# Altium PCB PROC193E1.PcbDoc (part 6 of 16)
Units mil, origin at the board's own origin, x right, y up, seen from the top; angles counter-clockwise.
Board outline 7700 x 2300 mil, 6 copper layers (Top Layer, GND 1, SIG 1, PWR, GND 2, Bottom Layer), stack 60.98 mil thick; 946 components, 667 nets, 9401 pads, 1730 vias.
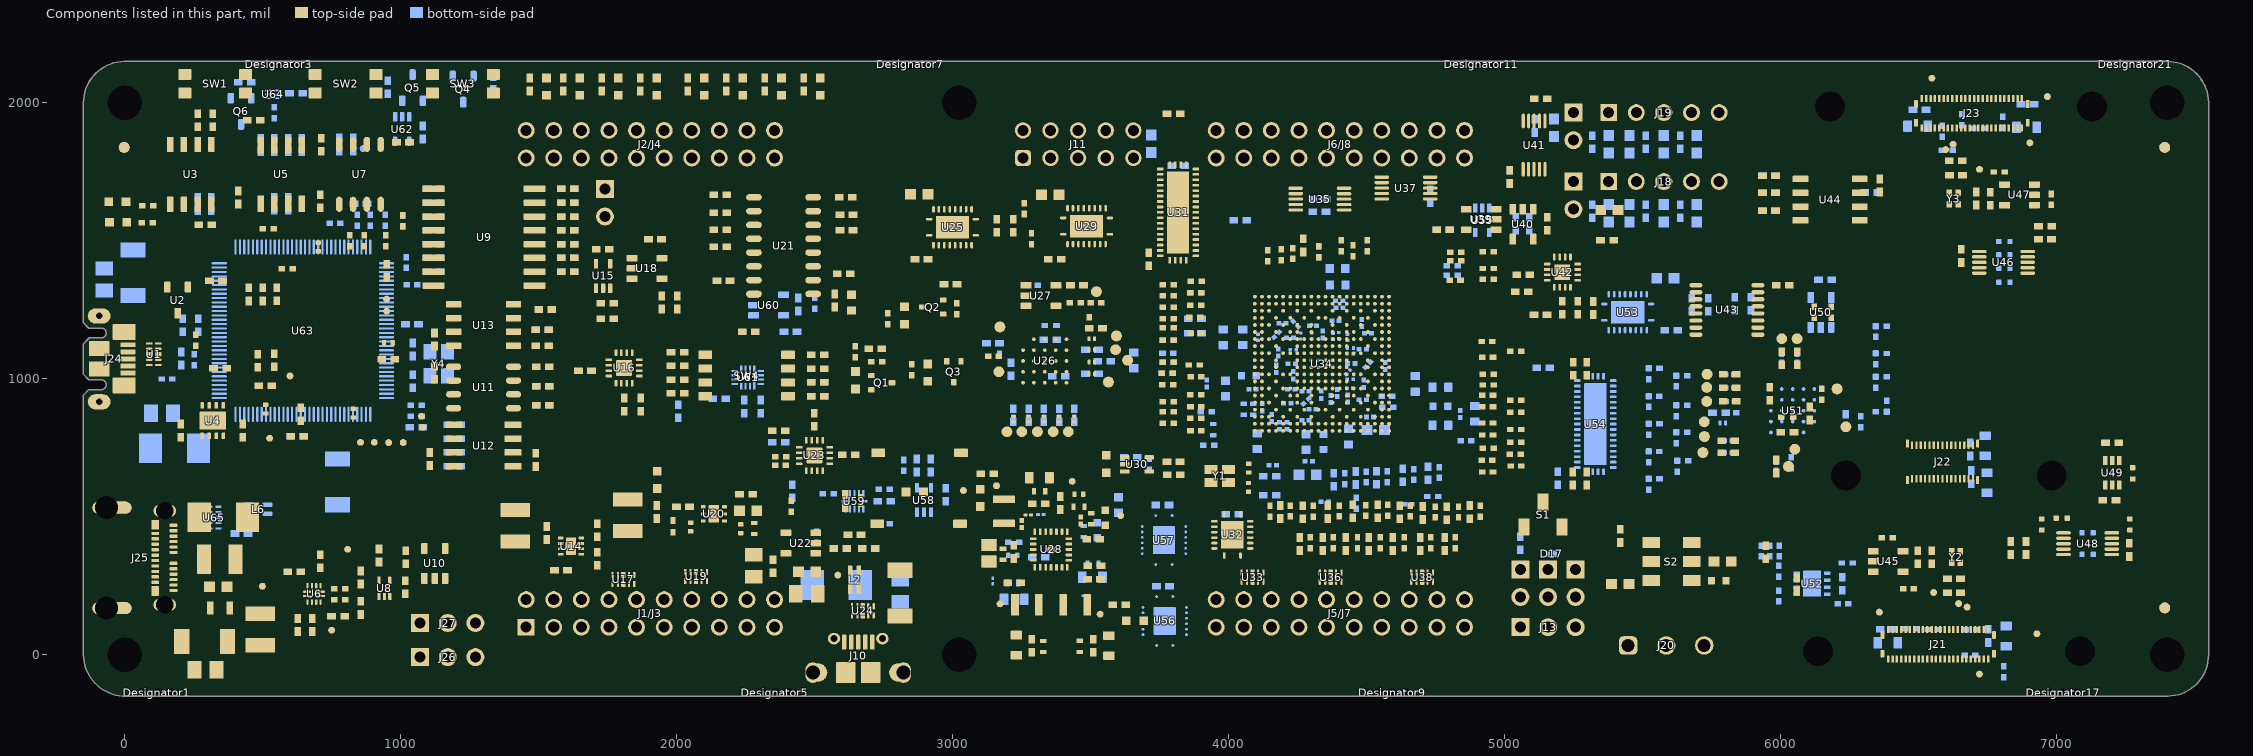
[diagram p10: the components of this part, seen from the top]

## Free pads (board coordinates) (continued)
  round 4 on Mech16: 1(-109,1797) 1(-109,1797) 1(-107,1890) 1(-107,1890) 1(-100.21,1451.4) 1(-100.21,1451.4) 1(-100.21,1501.4) 1(-100.21,1501.4) 1(-96.98,1641.17) 1(-96.98,1641.17) 1(-94.03,1567.07) 1(-94.03,1567.07) 1(-92.91,1280.67) 1(-92.91,1280.67) 1(-51.58,1279.52) 1(-51.58,1279.52) 1(-50.21,1451.4) 1(-50.21,1451.4) 1(-50.21,1501.4) 1(-50.21,1501.4) 1(10.71,1255.26) 1(10.71,1255.26) 1(55.5,1255.13) 1(55.5,1255.13) 1(57.05,333.66) 1(57.05,333.66) 1(57.05,369.66) 1(57.05,369.66) 1(58.94,1123.11) 1(58.94,1123.11) 1(69.85,292.13) 1(69.85,292.13) 1(76.14,1007.82) 1(76.14,1007.82) 1(80.09,231.18) 1(80.09,231.18) 1(80.09,471.33) 1(80.09,471.33) 1(95.75,923.11) 1(95.75,923.11) 1(104.21,999.27) 1(104.21,999.27) 1(130.97,1565.68) 1(130.97,1565.68) 1(133.02,1626.75) 1(133.02,1626.75) 1(140.74,333.26) 1(140.74,333.26) 1(140.74,369.26) 1(140.74,369.26) 1(142.29,400.06) 1(142.29,400.06) 1(143.88,424.98) 1(143.88,424.98) 1(144,473) 1(144,473) 1(144,282.09) 1(144,282.09) 1(145,2110) 1(145,2110) 1(155,1370.91) 1(155,1370.91) 1(160,1041.39) 1(160,1041.39) 1(160,1077.39) 1(160,1077.39) 1(163.9,1892.59) 1(163.9,1892.59) 1(164,1678) 1(164,1678) 1(165,1203.44) 1(165,1203.44) 1(174.9,1129.75) 1(174.9,1129.75) 1(175.1,-66.69) 1(175.1,-66.69) 1(175.1,-38.02) 1(175.1,-38.02) 1(183.7,107.99) 1(183.7,107.99) 1(198.93,220.48) 1(198.93,220.48) 1(202.72,681.67) 1(202.72,681.67) 1(203.76,-66.69) 1(203.76,-66.69) 1(203.76,-38.02) 1(203.76,-38.02) 1(212.36,107.99) 1(212.36,107.99) 1(212.56,390.13) 1(212.56,390.13) 1(213.57,1689.72) 1(213.57,1689.72) 1(218.04,259.4) 1(218.04,259.4) 1(223.39,199.95) 1(223.39,199.95) 1(231.43,1558.65) 1(231.43,1558.65) 1(240.71,229.19) 1(240.71,229.19) 1(240.71,292.2) 1(240.71,292.2) 1(240.71,325.66) 1(240.71,325.66) 1(241.5,360.53) 1(241.5,360.53) 1(243.58,167.7) 1(243.58,167.7) 1(243.98,959.49) 1(243.98,959.49) 1(245,993.11) 1(245,993.11) 1(261.88,2035.35) 1(261.88,2035.35) 1(263.8,258.72) 1(263.8,258.72) 1(264.06,1690.56) 1(264.06,1690.56) 1(264.16,200.22) 1(264.16,200.22) 1(265.82,1248.11) 1(265.82,1248.11) 1(274.55,1355.66) 1(274.55,1355.66) 1(280.11,952.74) 1(280.11,952.74) 1(291.26,1020) 1(291.26,1020) 1(294.7,1182.06) 1(294.7,1182.06) 1(296.51,1127.49) 1(296.51,1127.49) 1(296.51,1323.98) 1(296.51,1323.98) 1(315,1524) 1(315,1524) 1(318.73,1989.01) 1(318.73,1989.01) 1(319,-115) 1(319,-115) 1(350.09,1913.44) 1(350.09,1913.44) 1(353.19,2035.93) 1(353.19,2035.93) 1(377.93,2074.5) 1(377.93,2074.5) 1(382.15,1633.29) 1(382.15,1633.29) 1(386.18,977.52) 1(386.18,977.52) 1(390,1166.68) 1(390,1166.68) 1(390,1355.66) 1(390,1355.66) 1(395,826.17) 1(395,826.17) 1(395,1078.07) 1(395,1078.07) 1(400,1038.47) 1(400,1038.47) 1(408.56,246.92) 1(408.56,246.92) 1(408.56,275.59) 1(408.56,275.59) 1(419,-115) 1(419,-115) 1(421.14,1884.01) 1(421.14,1884.01) 1(423.01,-47.42) 1(423.01,-47.42) 1(423.01,-18.76) 1(423.01,-18.76) 1(434.84,276.57) 1(434.84,276.57) 1(436.18,977.52) 1(436.18,977.52) 1(444.71,1680.54) 1(444.71,1680.54) 1(448.04,304.9) 1(448.04,304.9) 1(448.04,333.56) 1(448.04,333.56) 1(448.04,362.23) 1(448.04,362.23) 1(448.04,390.89) 1(448.04,390.89) 1(450.31,190.05) 1(450.31,190.05) 1(450.31,218.71) 1(450.31,218.71) 1(451.67,-47.42) 1(451.67,-47.42) 1(451.67,-18.76) 1(451.67,-18.76) 1(453.93,1387.9) 1(453.93,1387.9) 1(457.27,797.27) 1(457.27,797.27) 1(457.48,764.8) 1(457.48,764.8) 1(461.61,1870.74) 1(461.61,1870.74) 1(476.71,304.9) 1(476.71,304.9) 1(476.71,333.56) 1(476.71,333.56) 1(476.71,362.23) 1(476.71,362.23) 1(476.71,390.89) 1(476.71,390.89) 1(478.98,190.05) 1(478.98,190.05) 1(478.98,218.71) 1(478.98,218.71) 1(480.33,-47.42) 1(480.33,-47.42) 1(480.33,-18.76) 1(480.33,-18.76) 1(480.59,1413.28) 1(480.59,1413.28) 1(480.73,784.53) 1(480.73,784.53) 1(481.97,1122.33) 1(481.97,1122.33) 1(485.53,2102.28) 1(485.53,2102.28) 1(488.92,2041.18) 1(488.92,2041.18) 1(489.98,1959.79) 1(489.98,1959.79) 1(496.08,823.57) 1(496.08,823.57) 1(499.83,1519.85) 1(499.83,1519.85) 1(500.77,1367.28) 1(500.77,1367.28) 1(504.73,481.52) 1(504.73,481.52) 1(507.64,190.05) 1(507.64,190.05) 1(507.64,218.71) 1(507.64,218.71) 1(509,-47.42) 1(509,-47.42) 1(509,-18.76) 1(509,-18.76) 1(510.2,934.01) 1(510.2,934.01) 1(513.14,2068) 1(513.14,2068) 1(519,-115) 1(519,-115) 1(530.73,1008.1) 1(530.73,1008.1) 1(536.3,190.05) 1(536.3,190.05) 1(536.3,218.71) 1(536.3,218.71) 1(536.3,247.37) 1(536.3,247.37) 1(537.66,-47.42) 1(537.66,-47.42) 1(537.66,-18.76) 1(537.66,-18.76) 1(537.79,1365.91) 1(537.79,1365.91) 1(539.2,416.22) 1(539.2,416.22) 1(539.2,1519.68) 1(539.2,1519.68) 1(541.82,1907.98) 1(541.82,1907.98) 1(541.97,1124.26) 1(541.97,1124.26) 1(541.97,1572.04) 1(541.97,1572.04) 1(563.03,1429.89) 1(563.03,1429.89) 1(564.96,190.05) 1(564.96,190.05) 1(564.96,218.71) 1(564.96,218.71) 1(573.46,1983.42) 1(573.46,1983.42) 1(590.41,340.66) 1(590.41,340.66) 1(591.69,1689.01) 1(591.69,1689.01) 1(591.82,1570.46) 1(591.82,1570.46) 1(591.82,1907.98) 1(591.82,1907.98) 1(597.02,2064.5) 1(597.02,2064.5) 1(598.48,823) 1(598.48,823) 1(598.48,1043.83) 1(598.48,1043.83) 1(608.14,1979.7) 1(608.14,1979.7) 1(608.19,1427.13) 1(608.19,1427.13) 1(619,-115) 1(619,-115) 1(622.03,205.39) 1(622.03,205.39) 1(622.36,237.37) 1(622.36,237.37) 1(627.14,50.91) 1(627.14,50.91) 1(636.73,333.56) 1(636.73,333.56) 1(637.63,927.56) 1(637.63,927.56) 1(641.56,1907.98) 1(641.56,1907.98) 1(641.82,1573.46) 1(641.82,1573.46) 1(650.96,1410.49) 1(650.96,1410.49) 1(654.75,1363.22) 1(654.75,1363.22) 1(663.07,822.16) 1(663.07,822.16) 1(668,-60) 1(668,-60) 1(673.06,1870.74) 1(673.06,1870.74) 1(679.97,48.23) 1(679.97,48.23) 1(680.93,1825.27) 1(680.93,1825.27) 1(689.76,1992.44) 1(689.76,1992.44) 1(690.5,798) 1(690.5,798) 1(693.44,275.6) 1(693.44,275.6) 1(700.81,1429.87) 1(700.81,1429.87) 1(700.81,1526.55) 1(700.81,1526.55) 1(708.51,543.88) 1(708.51,543.88) 1(708.51,709.23) 1(708.51,709.23) 1(708.51,1582.82) 1(708.51,1582.82) 1(711.42,1905.81) 1(711.42,1905.81) 1(719,-115) 1(719,-115) 1(740,951.65) 1(740,951.65) 1(740,987.65) 1(740,987.65) 1(740.37,1667.24) 1(740.37,1667.24) 1(741.85,363.15) 1(741.85,363.15) 1(742.1,1536.63) 1(742.1,1536.63) 1(748.05,1429.87) 1(748.05,1429.87) 1(768,-60) 1(768,-60) 1(776.99,1908.23) 1(776.99,1908.23) 1(779,2072) 1(779,2072) 1(798.91,167.7) 1(798.91,167.7) 1(804.99,1587.77) 1(804.99,1587.77) 1(815,1415.6) 1(815,1415.6) 1(815.77,1545.65) 1(815.77,1545.65) 1(819,-115) 1(819,-115) 1(826.42,918.87) 1(826.42,918.87) 1(827.25,1907.72) 1(827.25,1907.72) 1(827.49,824.51) 1(827.49,824.51) 1(828.6,543.88) 1(828.6,543.88) 1(828.6,709.23) 1(828.6,709.23) 1(830.33,1685.11) 1(830.33,1685.11) 1(831,2000) 1(831,2000) 1(843.5,1134.61) 1(843.5,1134.61) 1(853.9,798.54) 1(853.9,798.54) 1(861.83,1229.53) 1(861.83,1229.53) 1(866.99,1429.87) 1(866.99,1429.87) 1(868,-60) 1(868,-60) 1(870.44,1181.03) 1(870.44,1181.03) 1(877.09,1676.14) 1(877.09,1676.14) 1(880.29,336.27) 1(880.29,336.27) 1(885.16,146.38) 1(885.16,146.38) 1(888.6,1260.98) 1(888.6,1260.98) 1(892.5,1303.29) 1(892.5,1303.29) 1(898.28,1131.06) 1(898.28,1131.06) 1(899.81,1071.82) 1(899.81,1071.82) 1(899.81,1024.58) 1(899.81,1024.58) 1(900.47,1907.56) 1(900.47,1907.56) 1(901,1355.28) 1(901,1355.28) 1(901,1402.53) 1(901,1402.53) 1(903.32,1230.74) 1(903.32,1230.74) 1(903.9,798.54) 1(903.9,798.54) 1(910.24,2000) 1(910.24,2000) 1(915,1555) 1(915,1555) 1(919,-115) 1(919,-115) 1(927.09,1676.14) 1(927.09,1676.14) 1(945.89,1453.83) 1(945.89,1453.83) 1(952.36,1998.29) 1(952.36,1998.29) 1(953.18,383.51) 1(953.18,383.51) 1(955.9,797.54) 1(955.9,797.54) 1(956.83,1910.76) 1(956.83,1910.76) 1(960.37,178.53) 1(960.37,178.53) 1(968,-60) 1(968,-60) 1(971.1,1555) 1(971.1,1555) 1(974.31,1594.37) 1(974.31,1594.37) 1(980.29,1891.03) 1(980.29,1891.03) 1(994.37,1245.24) 1(994.37,1245.24) 1(999.04,1120) 1(999.04,1120) 1(999.04,1371.22) 1(999.04,1371.22) 1(999.09,1010.35) 1(999.09,1010.35) 1(1000,797.13) 1(1000,797.13) 1(1000,2096.74) 1(1000,2096.74) 1(1003.44,1166.68) 1(1003.44,1166.68) 1(1007.93,1622.51) 1(1007.93,1622.51) 1(1008.9,1090.98) 1(1008.9,1090.98) 1(1016.88,413.97) 1(1016.88,413.97) 1(1019,-115) 1(1019,-115) 1(1029.86,1552.95) 1(1029.86,1552.95) 1(1032.23,1900.79) 1(1032.23,1900.79) 1(1042.72,2064.5) 1(1042.72,2064.5) 1(1043.03,221.53) 1(1043.03,221.53) 1(1043.03,1166.68) 1(1043.03,1166.68) 1(1049.4,330.18) 1(1049.4,330.18) 1(1052.8,1439.6) 1(1052.8,1439.6) 1(1058.6,1591.68) 1(1058.6,1591.68) 1(1058.6,1639.54) 1(1058.6,1639.54) 1(1058.6,1688.24) 1(1058.6,1688.24) 1(1059.56,1387.43) 1(1059.56,1387.43) 1(1059.56,1490.13) 1(1059.56,1490.13) 1(1059.56,1536.84) 1(1059.56,1536.84) 1(1068,-60) 1(1068,-60) 1(1072,682.5) 1(1072,682.5) 1(1074.64,729.43) 1(1074.64,729.43) 1(1079.12,796.57) 1(1079.12,796.57) 1(1087.59,1142.48) 1(1087.59,1142.48) 1(1100.09,1197.99) 1(1100.09,1197.99) 1(1106.33,904.21) 1(1106.33,904.21) 1(1110.3,864.22) 1(1110.3,864.22) 1(1111.97,1910.99) 1(1111.97,1910.99) 1(1119,-115) 1(1119,-115) 1(1122.11,962.95) 1(1122.11,962.95) 1(1124.06,319.66) 1(1124.06,319.66) 1(1134.25,833.06) 1(1134.25,833.06) 1(1134.47,783.03) 1(1134.47,783.03) 1(1137.37,732.59) 1(1137.37,732.59) 1(1141.85,1220.52) 1(1141.85,1220.52) 1(1154.29,2035.35) 1(1154.29,2035.35) 1(1160.43,317.22) 1(1160.43,317.22) 1(1160.43,425.78) 1(1160.43,425.78) 1(1168,-60) 1(1168,-60) 1(1177.39,1538.54) 1(1177.39,1538.54) 1(1177.39,1587.95) 1(1177.39,1587.95) 1(1177.39,1636.27) 1(1177.39,1636.27) 1(1177.39,1689.4) 1(1177.39,1689.4) 1(1178.78,1387.95) 1(1178.78,1387.95) 1(1178.78,1437.95) 1(1178.78,1437.95) 1(1178.78,1487.95) 1(1178.78,1487.95) 1(1193.7,863.35) 1(1193.7,863.35) 1(1219,-115) 1(1219,-115) 1(1237.41,893.59) 1(1237.41,893.59) 1(1237.64,1269.73) 1(1237.64,1269.73) 1(1241.03,1337.95) 1(1241.03,1337.95) 1(1243.83,321.32) 1(1243.83,321.32) 1(1243.83,371.32) 1(1243.83,371.32) 1(1243.83,421.32) 1(1243.83,421.32) 1(1252.55,833.03) 1(1252.55,833.03) 1(1252.93,683.03) 1(1252.93,683.03) 1(1257.62,2002.26) 1(1257.62,2002.26) 1(1278.83,321.32) 1(1278.83,321.32) 1(1278.83,371.32) 1(1278.83,371.32) 1(1278.83,421.32) 1(1278.83,421.32) 1(1298.34,2035.23) 1(1298.34,2035.23) 1(1313.83,321.32) 1(1313.83,321.32) 1(1313.83,371.32) 1(1313.83,371.32) 1(1313.83,421.32) 1(1313.83,421.32) 1(1319,-115) 1(1319,-115) 1(1348.83,321.32) 1(1348.83,321.32) 1(1348.83,371.32) 1(1348.83,371.32) 1(1348.83,421.32) 1(1348.83,421.32) 1(1356,1075) 1(1356,1075) 1(1360,1376) 1(1360,1376) 1(1363.22,834.47) 1(1363.22,834.47) 1(1363.22,893.59) 1(1363.22,893.59) 1(1366,-59) 1(1366,-59) 1(1369,1914) 1(1369,1914) 1(1373,1874) 1(1373,1874) 1(1377.8,2101) 1(1377.8,2101) 1(1377.8,2050.63) 1(1377.8,2050.63) 1(1417.18,573.29) 1(1417.18,573.29) 1(1419,-115) 1(1419,-115) 1(1453.12,733.03) 1(1453.12,733.03) 1(1454.1,784.53) 1(1454.1,784.53) 1(1454.17,1269.73) 1(1454.17,1269.73) 1(1458.14,1218.93) 1(1458.14,1218.93) 1(1466,-59) 1(1466,-59) 1(1467.18,573.29) 1(1467.18,573.29) 1(1476.35,2001.53) 1(1476.35,2001.53) 1(1489.23,1088.54) 1(1489.23,1088.54) 1(1490.37,870.15) 1(1490.37,870.15) 1(1490.37,1012.4) 1(1490.37,1012.4) 1(1509.54,1218.26) 1(1509.54,1218.26) 1(1517.18,573.29) 1(1517.18,573.29) 1(1517.85,532.07) 1(1517.85,532.07) 1(1519,-115) 1(1519,-115) 1(1520.75,683.03) 1(1520.75,683.03) 1(1520.75,729.75) 1(1520.75,729.75) 1(1521.89,305.62) 1(1521.89,305.62) 1(1537.64,1012.4) 1(1537.64,1012.4) 1(1543.62,1337.95) 1(1543.62,1337.95) 1(1551,1711) 1(1551,1711) 1(1566,-59) 1(1566,-59) 1(1567.18,573.29) 1(1567.18,573.29) 1(1567.18,531.07) 1(1567.18,531.07) 1(1572.35,902.82) 1(1572.35,902.82) 1(1572.35,973.37) 1(1572.35,973.37) 1(1573.23,1177.74) 1(1573.23,1177.74) 1(1575.69,342.77) 1(1575.69,342.77) 1(1576.68,1119.73) 1(1576.68,1119.73) 1(1580.01,1251.09) 1(1580.01,1251.09) 1(1581.16,1355.28) 1(1581.16,1355.28) 1(1587.87,2010) 1(1587.87,2010) 1(1607.16,1029.69) 1(1607.16,1029.69) 1(1614.73,342.34) 1(1614.73,342.34) 1(1617.18,573.29) 1(1617.18,573.29) 1(1617.18,531.07) 1(1617.18,531.07) 1(1619,-115) 1(1619,-115) 1(1642.89,307.35) 1(1642.89,307.35) 1(1663.62,1445.86) 1(1663.62,1445.86) 1(1663.62,1587.95) 1(1663.62,1587.95) 1(1663.62,1387.95) 1(1663.62,1387.95) 1(1663.62,1487.95) 1(1663.62,1487.95) 1(1663.62,1537.95) 1(1663.62,1537.95) 1(1663.62,1637.95) 1(1663.62,1637.95) 1(1665.57,532.27) 1(1665.57,532.27) 1(1666,-59) 1(1666,-59) 1(1667.18,573.29) 1(1667.18,573.29) 1(1673,1707) 1(1673,1707) 1(1691,2099) 1(1691,2099) 1(1706.73,1505.08) 1(1706.73,1505.08) 1(1710.81,297.92) 1(1710.81,297.92) 1(1717.18,530.69) 1(1717.18,530.69) 1(1717.18,573.29) 1(1717.18,573.29) 1(1719,-115) 1(1719,-115) 1(1726.09,1010.01) 1(1726.09,1010.01) 1(1727.87,2010) 1(1727.87,2010) 1(1744.18,290.16) 1(1744.18,290.16) 1(1747.95,957.83) 1(1747.95,957.83) 1(1747.98,322.44) 1(1747.98,322.44) 1(1758.55,1360.32) 1(1758.55,1360.32) 1(1762.88,374.08) 1(1762.88,374.08) 1(1766,-59) 1(1766,-59) 1(1776.86,883.47) 1(1776.86,883.47) 1(1777.33,930.1) 1(1777.33,930.1) 1(1779.99,398.69) 1(1779.99,398.69) 1(1790.8,1469.23) 1(1790.8,1469.23) 1(1796.54,1362.48) 1(1796.54,1362.48) 1(1800.59,374.08) 1(1800.59,374.08) 1(1803,1218) 1(1803,1218) 1(1806.54,319.63) 1(1806.54,319.63) 1(1818.66,398.69) 1(1818.66,398.69) 1(1818.97,1129.8) 1(1818.97,1129.8) 1(1819,-115) 1(1819,-115) 1(1831,2102) 1(1831,2102) 1(1838.63,374.08) 1(1838.63,374.08) 1(1848.83,321.95) 1(1848.83,321.95) 1(1857.07,398.69) 1(1857.07,398.69) 1(1866,-59) 1(1866,-59) 1(1867.87,2010) 1(1867.87,2010) 1(1876.49,374.08) 1(1876.49,374.08) 1(1876.62,806.99) 1(1876.62,806.99) 1(1888.17,299.13) 1(1888.17,299.13) 1(1888.79,882.86) 1(1888.79,882.86) 1(1888.79,965.11) 1(1888.79,965.11) 1(1893.55,398.69) 1(1893.55,398.69) 1(1896.32,1562.73) 1(1896.32,1562.73) 1(1896.53,1255.29) 1(1896.53,1255.29) 1(1897.51,1481.55) 1(1897.51,1481.55) 1(1903.16,657.22) 1(1903.16,657.22) 1(1913.96,427.52) 1(1913.96,427.52) 1(1914.55,374.08) 1(1914.55,374.08) 1(1919,-115) 1(1919,-115) 1(1933.18,398.69) 1(1933.18,398.69) 1(1936.3,859.93) 1(1936.3,859.93) 1(1942.64,898.21) 1(1942.64,898.21) 1(1944.75,1535.77) 1(1944.75,1535.77) 1(1949.19,374.08) 1(1949.19,374.08) 1(1950.36,1097.68) 1(1950.36,1097.68) 1(1951.13,936.88) 1(1951.13,936.88) 1(1951.13,996.31) 1(1951.13,996.31) 1(1951.13,1046.99) 1(1951.13,1046.99) 1(1959.64,1594.22) 1(1959.64,1594.22) 1(1965.79,536.03) 1(1965.79,536.03) 1(1966,-59) 1(1966,-59) 1(1986,2103) 1(1986,2103) 1(1986.19,417.66) 1(1986.19,417.66) 1(1998.65,313.65) 1(1998.65,313.65) 1(2002.86,1633.95) 1(2002.86,1633.95) 1(2017.2,385.96) 1(2017.2,385.96) 1(2019,-115) 1(2019,-115) 1(2033.9,859.16) 1(2033.9,859.16) 1(2034.38,1286.04) 1(2034.38,1286.04) 1(2034.72,908.61) 1(2034.72,908.61) 1(2039.29,2010) 1(2039.29,2010) 1(2047.23,568.72) 1(2047.23,568.72) 1(2050.18,417.66) 1(2050.18,417.66) 1(2061.23,936.88) 1(2061.23,936.88) 1(2061.23,986.88) 1(2061.23,986.88) 1(2061.23,1031.88) 1(2061.23,1031.88) 1(2061.23,1091.88) 1(2061.23,1091.88) 1(2066,-59) 1(2066,-59) 1(2070.03,323.6) 1(2070.03,323.6) 1(2096.84,1478.99) 1(2096.84,1478.99) 1(2096.84,1675.74) 1(2096.84,1675.74) 1(2101.49,1598.74) 1(2101.49,1598.74) 1(2104.27,336.69) 1(2104.27,336.69) 1(2107.91,1533.45) 1(2107.91,1533.45) 1(2114.42,1357.47) 1(2114.42,1357.47) 1(2119,-115) 1(2119,-115) 1(2142,2104) 1(2142,2104) 1(2143.24,382.33) 1(2143.24,382.33) 1(2166,-59) 1(2166,-59) 1(2173.02,1266.42) 1(2173.02,1266.42) 1(2179.29,2010) 1(2179.29,2010) 1(2192.97,1323.1) 1(2192.97,1323.1) 1(2196.39,1170.68) 1(2196.39,1170.68) 1(2200.65,442.95) 1(2200.65,442.95) 1(2203.89,232.77) 1(2203.89,232.77) 1(2215.76,917.37) 1(2215.76,917.37) 1(2219,-115) 1(2219,-115) 1(2221.19,338.39) 1(2221.19,338.39) 1(2222.08,387.7) 1(2222.08,387.7) 1(2227.27,1307.42) 1(2227.27,1307.42) 1(2231.35,1207.91) 1(2231.35,1207.91) 1(2265.29,1003.71) 1(2265.29,1003.71) 1(2266,-59) 1(2266,-59) 1(2274.42,770.71) 1(2274.42,770.71) 1(2281,2107) 1(2281,2107) 1(2304.25,959.03) 1(2304.25,959.03) 1(2308.09,582.06) 1(2308.09,582.06) 1(2313.09,1170.68) 1(2313.09,1170.68) 1(2314.55,442.95) 1(2314.55,442.95) 1(2316.06,481.55) 1(2316.06,481.55) 1(2319.29,2010) 1(2319.29,2010) 1(2322.76,1289.3) 1(2322.76,1289.3) 1(2325.69,707.38) 1(2325.69,707.38) 1(2329.67,926.4) 1(2329.67,926.4) 1(2332.6,875.54) 1(2332.6,875.54) 1(2345.05,481.55) 1(2345.05,481.55) 1(2353.24,1197.58) 1(2353.24,1197.58) 1(2356,662) 1(2356,662) 1(2366,-59) 1(2366,-59) 1(2377.9,842.25) 1(2377.9,842.25) 1(2379,1546) 1(2379,1546) 1(2380,1460) 1(2380,1460) 1(2380.17,565.14) 1(2380.17,565.14) 1(2395.05,656.33) 1(2395.05,656.33) 1(2395.21,744.52) 1(2395.21,744.52) 1(2412.04,843.84) 1(2412.04,843.84) 1(2421,2108) 1(2421,2108) 1(2440.44,1211.97) 1(2440.44,1211.97) 1(2443.56,1357.47) 1(2443.56,1357.47) 1(2450.95,541.93) 1(2450.95,541.93) 1(2457.71,853.56) 1(2457.71,853.56) 1(2459.29,2010) 1(2459.29,2010) 1(2459.58,402.06) 1(2459.58,402.06) 1(2460.3,623.46) 1(2460.3,623.46) 1(2470.62,1170.68) 1(2470.62,1170.68) 1(2490.18,582.06) 1(2490.18,582.06) 1(2499.01,1217.89) 1(2499.01,1217.89) 1(2503.91,127.19) 1(2503.91,127.19) 1(2503.91,156.78) 1(2503.91,156.78) 1(2508.54,639.98) 1(2508.54,639.98) 1(2518.8,494.68) 1(2518.8,494.68) 1(2531.83,1276.32) 1(2531.83,1276.32) 1(2532.68,875.72) 1(2532.68,875.72) 1(2534,1117) 1(2534,1117) 1(2539.92,844.52) 1(2539.92,844.52) 1(2541.01,405.42) 1(2541.01,405.42) 1(2550.3,156.78) 1(2550.3,156.78) 1(2550.94,127.19) 1(2550.94,127.19) 1(2560.77,611.42) 1(2560.77,611.42) 1(2561.96,666.9) 1(2561.96,666.9) 1(2565,2110) 1(2565,2110) 1(2566.86,1199.12) 1(2566.86,1199.12) 1(2567.3,936.88) 1(2567.3,936.88) 1(2568.43,1009.61) 1(2568.43,1009.61) 1(2570.28,971.88) 1(2570.28,971.88) 1(2575.47,869.52) 1(2575.47,869.52) 1(2602.17,789.9) 1(2602.17,789.9) 1(2604.74,1250.89) 1(2604.74,1250.89) 1(2611.47,475.4) 1(2611.47,475.4) 1(2618.69,1192.5) 1(2618.69,1192.5) 1(2622.08,1346.94) 1(2622.08,1346.94) 1(2628.07,880.01) 1(2628.07,880.01) 1(2631,1411.69) 1(2631,1411.69) 1(2632.78,1221.86) 1(2632.78,1221.86) 1(2635.46,1725.83) 1(2635.46,1725.83) 1(2640,2111) 1(2640,2111) 1(2643.73,500.17) 1(2643.73,500.17) 1(2643.73,613.01) 1(2643.73,613.01) 1(2647.7,790.46) 1(2647.7,790.46) 1(2651.55,1141.56) 1(2651.55,1141.56) 1(2666.65,1539.42) 1(2666.65,1539.42) 1(2668.26,1594.04) 1(2668.26,1594.04) 1(2671.37,1377.88) 1(2671.37,1377.88) 1(2673.3,120.95) 1(2673.3,120.95) 1(2674.47,475.4) 1(2674.47,475.4) 1(2687.67,677.7) 1(2687.67,677.7) 1(2703.14,90.7) 1(2703.14,90.7) 1(2709.37,1138.15) 1(2709.37,1138.15) 1(2723,2112) 1(2723,2112) 1(2726.22,438.36) 1(2726.22,438.36) 1(2730.44,659.54) 1(2730.44,659.54) 1(2740.79,1242.07) 1(2740.79,1242.07) 1(2754.96,799.79) 1(2754.96,799.79) 1(2779.73,1010.72) 1(2779.73,1010.72) 1(2791.54,858.68) 1(2791.54,858.68) 1(2796.71,795.12) 1(2796.71,795.12) 1(2806.96,552.14) 1(2806.96,552.14) 1(2807.92,474.79) 1(2807.92,474.79) 1(2813.98,1764.39) 1(2813.98,1764.39) 1(2816.02,1547.3) 1(2816.02,1547.3) 1(2816.1,1296.81) 1(2816.1,1296.81) 1(2819.73,1583.71) 1(2819.73,1583.71) 1(2821,2098) 1(2821,2098) 1(2822.93,1896.22) 1(2822.93,1896.22) 1(2823.83,1113.91) 1(2823.83,1113.91) 1(2823.83,1854.29) 1(2823.83,1854.29) 1(2846.02,1722.5) 1(2846.02,1722.5) 1(2851.59,1079.89) 1(2851.59,1079.89) 1(2856.14,1299.07) 1(2856.14,1299.07) 1(2859,2017) 1(2859,2017) 1(2861.3,373.59) 1(2861.3,373.59) 1(2863.13,1398.63) 1(2863.13,1398.63) 1(2864,212.66) 1(2864,212.66) 1(2864.13,1196.48) 1(2864.13,1196.48) 1(2869.72,463.8) 1(2869.72,463.8) 1(2869.72,1160.83) 1(2869.72,1160.83) 1(2882.7,333.2) 1(2882.7,333.2) 1(2883.18,747.07) 1(2883.18,747.07) 1(2884.33,188.76) 1(2884.33,188.76) 1(2885.02,1840.05) 1(2885.02,1840.05) 1(2892.39,1108.79) 1(2892.39,1108.79) 1(2895.9,373.18) 1(2895.9,373.18) 1(2895.94,711.03) 1(2895.94,711.03) 1(2898.74,1300.24) 1(2898.74,1300.24) 1(2899.31,1195.75) 1(2899.31,1195.75) 1(2901.02,1737.65) 1(2901.02,1737.65) 1(2903.06,212.32) 1(2903.06,212.32) 1(2910.13,1398.63) 1(2910.13,1398.63) 1(2911,460) 1(2911,460) 1(2916.35,333.2) 1(2916.35,333.2) 1(2920.18,187.94) 1(2920.18,187.94) 1(2923.83,934) 1(2923.83,934) 1(2924.11,561.51) 1(2924.11,561.51) 1(2929.28,372.56) 1(2929.28,372.56) 1(2929.87,1105.56) 1(2929.87,1105.56) 1(2937.28,213.35) 1(2937.28,213.35) 1(2952.99,332.7) 1(2952.99,332.7) 1(2954.99,188.91) 1(2954.99,188.91) 1(2960.23,646.74) 1(2960.23,646.74) 1(2962.07,1122.12) 1(2962.07,1122.12) 1(2970.51,1809.83) 1(2970.51,1809.83) 1(2987.21,1398.28) 1(2987.21,1398.28) 1(2992.83,871) 1(2992.83,871) 1(2997.83,833) 1(2997.83,833) 1(2999.63,1123.11) 1(2999.63,1123.11) 1(3028.84,988.08) 1(3028.84,988.08) 1(3040.35,875.54) 1(3040.35,875.54) 1(3042.19,839.37) 1(3042.19,839.37) 1(3042.46,805.99) 1(3042.46,805.99) 1(3048.35,1441.73) 1(3048.35,1441.73) 1(3048.88,1344.26) 1(3048.88,1344.26) 1(3056.83,943) 1(3056.83,943) 1(3068.61,472.57) 1(3068.61,472.57) 1(3068.61,537.33) 1(3068.61,537.33) 1(3068.61,340.68) 1(3068.61,340.68) 1(3069.65,284.74) 1(3069.65,284.74) 1(3070.02,441) 1(3070.02,441) 1(3070.9,410.2) 1(3070.9,410.2) 1(3075.44,879.77) 1(3075.44,879.77) 1(3082.87,805.99) 1(3082.87,805.99) 1(3089,1656) 1(3089,1656) 1(3092.5,340.68) 1(3092.5,340.68) 1(3096.05,459.14) 1(3096.05,459.14) 1(3096.27,425.02) 1(3096.27,425.02) 1(3107.08,496.45) 1(3107.08,496.45) 1(3115.36,273.16) 1(3115.36,273.16) 1(3122.53,1222.25) 1(3122.53,1222.25) 1(3124.61,1150.95) 1(3124.61,1150.95) 1(3127.61,1060.13) 1(3127.61,1060.13) 1(3151,2111) 1(3151,2111) 1(3160,-109) 1(3160,-109) 1(3160.37,253.84) 1(3160.37,253.84) 1(3161.44,1604.32) 1(3161.44,1604.32) 1(3164.52,1490.8) 1(3164.52,1490.8) 1(3166.98,1053.93) 1(3166.98,1053.93) 1(3171.12,1156.62) 1(3171.12,1156.62) 1(3172.83,884) 1(3172.83,884) 1(3186.34,609.1) 1(3186.34,609.1) 1(3187.64,663.03) 1(3187.64,663.03) 1(3195.87,843.98) 1(3195.87,843.98) 1(3199.57,238.84) 1(3199.57,238.84) 1(3200.26,910.56) 1(3200.26,910.56) 1(3201.81,635.38) 1(3201.81,635.38) 1(3208,2051) 1(3208,2051) 1(3217.85,609.1) 1(3217.85,609.1) 1(3217.85,663.03) 1(3217.85,663.03) 1(3219.47,1448.31) 1(3219.47,1448.31) 1(3222.55,1604.92) 1(3222.55,1604.92) 1(3223.02,1499.34) 1(3223.02,1499.34) 1(3225.65,-31.4) 1(3225.65,-31.4) 1(3226.9,308.72) 1(3226.9,308.72) 1(3235.08,635.38) 1(3235.08,635.38) 1(3238.72,1048.62) 1(3238.72,1048.62) 1(3241.2,1011.73) 1(3241.2,1011.73) 1(3246.48,295.51) 1(3246.48,295.51) 1(3248.91,663.03) 1(3248.91,663.03) 1(3250.34,381.29) 1(3250.34,381.29) 1(3250.68,843.98) 1(3250.68,843.98) 1(3251.53,327.08) 1(3251.53,327.08) 1(3254.61,609.1) 1(3254.61,609.1) 1(3260.95,355.89) 1(3260.95,355.89) 1(3265.34,1204.75) 1(3265.34,1204.75) 1(3266,2109) 1(3266,2109) 1(3271.11,-35.02) 1(3271.11,-35.02) 1(3271.47,288.3) 1(3271.47,288.3) 1(3274.71,1396.93) 1(3274.71,1396.93) 1(3277.12,323.02) 1(3277.12,323.02) 1(3300,478.86) 1(3300,478.86) 1(3306.43,843.98) 1(3306.43,843.98) 1(3307.64,1364.45) 1(3307.64,1364.45) 1(3309.2,1523.69) 1(3309.2,1523.69) 1(3318.12,-33.99) 1(3318.12,-33.99) 1(3319.1,1626.17) 1(3319.1,1626.17) 1(3319.76,1117.29) 1(3319.76,1117.29) 1(3324.24,1490.98) 1(3324.24,1490.98) 1(3330.81,480.15) 1(3330.81,480.15) 1(3332.07,1216.58) 1(3332.07,1216.58) 1(3357,51) 1(3357,51) 1(3357,76) 1(3357,76) 1(3357,104) 1(3357,104) 1(3358.61,598.24) 1(3358.61,598.24) 1(3360.98,843.98) 1(3360.98,843.98) 1(3364,-34) 1(3364,-34) 1(3368,1627) 1(3368,1627) 1(3372.67,967.47) 1(3372.67,967.47) 1(3384,51) 1(3384,51) 1(3384,76) 1(3384,76) 1(3384.77,1387.08) 1(3384.77,1387.08) 1(3385,104) 1(3385,104) 1(3385.12,654.13) 1(3385.12,654.13) 1(3385.95,1117.47) 1(3385.95,1117.47) 1(3387.01,614.43) 1(3387.01,614.43) 1(3411.04,-33.97) 1(3411.04,-33.97) 1(3411.07,964.88) 1(3411.07,964.88) 1(3416.59,843.98) 1(3416.59,843.98) 1(3422.56,1680.77) 1(3422.56,1680.77) 1(3424.04,1363.09) 1(3424.04,1363.09) 1(3429.55,50.79) 1(3429.55,50.79) 1(3429.55,74.19) 1(3429.55,74.19) 1(3430.39,97.72) 1(3430.39,97.72) 1(3434.8,1650.39) 1(3434.8,1650.39) 1(3439.63,1143.88) 1(3439.63,1143.88) 1(3440.86,1068.67) 1(3440.86,1068.67) 1(3442.67,362.75) 1(3442.67,362.75) 1(3450.01,970.53) 1(3450.01,970.53) 1(3453.35,341.77) 1(3453.35,341.77) 1(3456.32,-34.14) 1(3456.32,-34.14) 1(3460.63,1288.32) 1(3460.63,1288.32) 1(3471.83,732) 1(3471.83,732) 1(3474.14,1685.18) 1(3474.14,1685.18) 1(3474.72,1646.56) 1(3474.72,1646.56) 1(3477.56,398.54) 1(3477.56,398.54) 1(3486.39,253.5) 1(3486.39,253.5) 1(3495.83,787) 1(3495.83,787) 1(3496.38,1338.74) 1(3496.38,1338.74) 1(3496.45,347.6) 1(3496.45,347.6) 1(3497.69,-33.04) 1(3497.69,-33.04) 1(3498,398) 1(3498,398) 1(3499.02,1250.73) 1(3499.02,1250.73) 1(3513,1656) 1(3513,1656) 1(3516.4,658.87) 1(3516.4,658.87) 1(3519.81,549.92) 1(3519.81,549.92) 1(3520.14,579.08) 1(3520.14,579.08) 1(3524.33,722.69) 1(3524.33,722.69) 1(3529.49,193.16) 1(3529.49,193.16) 1(3538.06,1250.73) 1(3538.06,1250.73) 1(3538.46,1681.57) 1(3538.46,1681.57) 1(3543.83,795) 1(3543.83,795) 1(3551.58,933.89) 1(3551.58,933.89) 1(3555.85,579.08) 1(3555.85,579.08) 1(3556.6,-32.52) 1(3556.6,-32.52) 1(3556.8,549.41) 1(3556.8,549.41) 1(3559.59,1153.58) 1(3559.59,1153.58) 1(3561.2,279.33) 1(3561.2,279.33) 1(3562.21,1016.53) 1(3562.21,1016.53) 1(3562.21,1105.54) 1(3562.21,1105.54) 1(3565.84,331.49) 1(3565.84,331.49) 1(3568.29,418.56) 1(3568.29,418.56) 1(3574.07,1253.47) 1(3574.07,1253.47) 1(3577.77,1191.54) 1(3577.77,1191.54) 1(3581.66,468.03) 1(3581.66,468.03) 1(3587.4,1622.59) 1(3587.4,1622.59) 1(3601.28,1481.55) 1(3601.28,1481.55) 1(3602.19,1067.09) 1(3602.19,1067.09) 1(3610.68,427.23) 1(3610.68,427.23) 1(3611.92,1441.47) 1(3611.92,1441.47) 1(3613,3) 1(3613,3) 1(3615.04,788.66) 1(3615.04,788.66) 1(3615.13,-29.28) 1(3615.13,-29.28) 1(3618.98,920.64) 1(3618.98,920.64) 1(3619.55,467.35) 1(3619.55,467.35) 1(3619.93,370.94) 1(3619.93,370.94) 1(3626.9,1125.13) 1(3626.9,1125.13) 1(3635.93,1647.79) 1(3635.93,1647.79) 1(3650.99,1460.27) 1(3650.99,1460.27) 1(3651.24,32.82) 1(3651.24,32.82) 1(3652.17,-5.73) 1(3652.17,-5.73) 1(3655.94,664.03) 1(3655.94,664.03) 1(3656,1533) 1(3656,1533) 1(3662.05,464.41) 1(3662.05,464.41) 1(3667.15,928.18) 1(3667.15,928.18) 1(3669.23,1698.3) 1(3669.23,1698.3) 1(3672.46,1657.28) 1(3672.46,1657.28) 1(3673.18,794.74) 1(3673.18,794.74) 1(3674.02,1437.64) 1(3674.02,1437.64) 1(3675.08,1603.66) 1(3675.08,1603.66) 1(3681.89,1513.05) 1(3681.89,1513.05) 1(3683.7,1408.2) 1(3683.7,1408.2) 1(3684,1027) 1(3684,1027) 1(3684.05,199.17) 1(3684.05,199.17) 1(3684.3,976.57) 1(3684.3,976.57) 1(3693.85,258.12) 1(3693.85,258.12) 1(3697.94,-47.44) 1(3697.94,-47.44) 1(3708.41,1694.68) 1(3708.41,1694.68) 1(3709.07,1655.63) 1(3709.07,1655.63) 1(3709.91,869.42) 1(3709.91,869.42) 1(3713.33,337.9) 1(3713.33,337.9) 1(3715.1,1504.55) 1(3715.1,1504.55) 1(3715.1,1543.92) 1(3715.1,1543.92) 1(3722.17,2049.21) 1(3722.17,2049.21) 1(3724.76,1112.61) 1(3724.76,1112.61) 1(3725.87,1008.49) 1(3725.87,1008.49) 1(3725.87,1742.47) 1(3725.87,1742.47) 1(3727.98,-44.75) 1(3727.98,-44.75) 1(3728.52,1052.25) 1(3728.52,1052.25) 1(3734.96,565.09) 1(3734.96,565.09) 1(3734.96,1260) 1(3734.96,1260) 1(3734.96,1339.91) 1(3734.96,1339.91) 1(3735.1,1300.51) 1(3735.1,1300.51) 1(3736.59,798.14) 1(3736.59,798.14) 1(3743.34,664.21) 1(3743.34,664.21) 1(3746.46,1927.53) 1(3746.46,1927.53) 1(3749.2,1412.38) 1(3749.2,1412.38) 1(3756.5,1813.95) 1(3756.5,1813.95) 1(3776.03,726.55) 1(3776.03,726.55) 1(3778.35,1878.42) 1(3778.35,1878.42) 1(3779.5,945.02) 1(3779.5,945.02) 1(3795.55,1814.06) 1(3795.55,1814.06) 1(3797.84,304.51) 1(3797.84,304.51) 1(3801,1931) 1(3801,1931) 1(3802.8,540.15) 1(3802.8,540.15) 1(3811.06,231.15) 1(3811.06,231.15) 1(3820.08,949.9) 1(3820.08,949.9) 1(3820.64,505.32) 1(3820.64,505.32) 1(3820.84,33.83) 1(3820.84,33.83) 1(3825.76,735.54) 1(3825.76,735.54) 1(3825.92,1039.21) 1(3825.92,1039.21) 1(3828.23,1278.09) 1(3828.23,1278.09) 1(3830.2,1911.63) 1(3830.2,1911.63) 1(3830.35,1320.53) 1(3830.35,1320.53) 1(3830.7,903.14) 1(3830.7,903.14) 1(3831.09,1000.05) 1(3831.09,1000.05) 1(3833.4,810.41) 1(3833.4,810.41) 1(3835.68,1820.3) 1(3835.68,1820.3) 1(3841.49,1360.7) 1(3841.49,1360.7) 1(3845.65,1869) 1(3845.65,1869) 1(3847.27,319.45) 1(3847.27,319.45) 1(3849.69,1116.73) 1(3849.69,1116.73) 1(3864.16,401.48) 1(3864.16,401.48) 1(3865.32,1421.32) 1(3865.32,1421.32) 1(3866.46,464.8) 1(3866.46,464.8) 1(3868.14,569.65) 1(3868.14,569.65) 1(3868.6,1813.52) 1(3868.6,1813.52) 1(3869.34,2015.99) 1(3869.34,2015.99) 1(3869.97,234.86) 1(3869.97,234.86) 1(3876.92,163.05) 1(3876.92,163.05) 1(3879.72,654.32) 1(3879.72,654.32) 1(3879.98,685.43) 1(3879.98,685.43) 1(3879.98,721.43) 1(3879.98,721.43) 1(3881.18,966.82) 1(3881.18,966.82) 1(3889.58,445.68) 1(3889.58,445.68) 1(3901.08,1089.99) 1(3901.08,1089.99) 1(3908.26,1544.21) 1(3908.26,1544.21) 1(3910.51,523.8) 1(3910.51,523.8) 1(3913.33,1662.03) 1(3913.33,1662.03) 1(3915.71,466.73) 1(3915.71,466.73) 1(3915.76,1453.42) 1(3915.76,1453.42) 1(3917.06,1504.83) 1(3917.06,1504.83) 1(3917.06,1583.29) 1(3917.06,1583.29) 1(3917.06,1622.66) 1(3917.06,1622.66) 1(3919.71,344.91) 1(3919.71,344.91) 1(3920.05,436.01) 1(3920.05,436.01) 1(3923.19,2015.88) 1(3923.19,2015.88) 1(3927.32,8.24) 1(3927.32,8.24) 1(3937.57,1165.74) 1(3937.57,1165.74) 1(3946,1661) 1(3946,1661) 1(3949.03,963.79) 1(3949.03,963.79) 1(3949.56,915.6) 1(3949.56,915.6) 1(3957.53,1623.1) 1(3957.53,1623.1) 1(3957.85,2013.56) 1(3957.85,2013.56) 1(3958.07,1581.14) 1(3958.07,1581.14) 1(3958.96,1077.54) 1(3958.96,1077.54) 1(3959.88,1470.35) 1(3959.88,1470.35) 1(3960.53,1542.59) 1(3960.53,1542.59) 1(3963.61,1423.04) 1(3963.61,1423.04) 1(3970.96,283.87) 1(3970.96,283.87) 1(3976.69,1236.43) 1(3976.69,1236.43) 1(3979.2,719.87) 1(3979.2,719.87) 1(4016.33,291.12) 1(4016.33,291.12) 1(4019.21,1373.59) 1(4019.21,1373.59) 1(4031.75,1755.68) 1(4031.75,1755.68) 1(4035.17,739.99) 1(4035.17,739.99) 1(4035.56,1670.76) 1(4035.56,1670.76) 1(4036.63,628.91) 1(4036.63,628.91) 1(4039.25,1334.87) 1(4039.25,1334.87) 1(4056.62,775.42) 1(4056.62,775.42) 1(4063.16,512.1) 1(4063.16,512.1) 1(4065.95,1544.8) 1(4065.95,1544.8) 1(4068.6,722.43) 1(4068.6,722.43) 1(4068.8,813.88) 1(4068.8,813.88) 1(4068.86,1303.93) 1(4068.86,1303.93) 1(4071.44,574.49) 1(4071.44,574.49) 1(4073,1471) 1(4073,1471) 1(4074.24,1411.06) 1(4074.24,1411.06) 1(4076.31,1365.36) 1(4076.31,1365.36) 1(4080.94,1699.37) 1(4080.94,1699.37) 1(4082.54,1762.04) 1(4082.54,1762.04) 1(4085.92,326.83) 1(4085.92,326.83) 1(4093.28,365.88) 1(4093.28,365.88) 1(4099.5,464.79) 1(4099.5,464.79) 1(4103,1427) 1(4103,1427) 1(4114.27,687.38) 1(4114.27,687.38) 1(4114.93,849.12) 1(4114.93,849.12) 1(4119.87,333.62) 1(4119.87,333.62) 1(4120.3,541.76) 1(4120.3,541.76) 1(4126.14,415.42) 1(4126.14,415.42) 1(4128.02,1949.51) 1(4128.02,1949.51) 1(4131.35,612.37) 1(4131.35,612.37) 1(4138.02,459.11) 1(4138.02,459.11) 1(4138.31,767.58) 1(4138.31,767.58) 1(4138.57,1106.76) 1(4138.57,1106.76) 1(4142.26,1045.03) 1(4142.26,1045.03) 1(4142.84,1210.99) 1(4142.84,1210.99) 1(4144.45,1166.96) 1(4144.45,1166.96) 1(4144.82,935.57) 1(4144.82,935.57) 1(4145.75,901.55) 1(4145.75,901.55) 1(4145.85,1001.47) 1(4145.85,1001.47) 1(4150,1070.91) 1(4150,1070.91) 1(4150.06,1508.43) 1(4150.06,1508.43) 1(4152.12,1629.94) 1(4152.12,1629.94) 1(4153.42,1597.1) 1(4153.42,1597.1) 1(4156.69,1551.25) 1(4156.69,1551.25) 1(4156.85,1125.25) 1(4156.85,1125.25) 1(4161.05,273.38) 1(4161.05,273.38) 1(4162.41,416.58) 1(4162.41,416.58) 1(4165.31,1235.75) 1(4165.31,1235.75) 1(4165.38,1188.34) 1(4165.38,1188.34) 1(4170.16,901.47) 1(4170.16,901.47) 1(4176,954.32) 1(4176,954.32) 1(4176.62,1004.36) 1(4176.62,1004.36) 1(4178.15,773.52) 1(4178.15,773.52) 1(4182.82,862.93) 1(4182.82,862.93) 1(4183.68,1138.06) 1(4183.68,1138.06) 1(4184.27,1255.87) 1(4184.27,1255.87) 1(4189.47,1053.85) 1(4189.47,1053.85) 1(4190.91,980.87) 1(4190.91,980.87) 1(4191.16,464.99) 1(4191.16,464.99) 1(4192.41,1971.23) 1(4192.41,1971.23) 1(4194.53,1223.15) 1(4194.53,1223.15) 1(4195,928) 1(4195,928) 1(4195.57,1114.94) 1(4195.57,1114.94) 1(4198,1080) 1(4198,1080) 1(4202.86,1029.9) 1(4202.86,1029.9) 1(4205.94,884.23) 1(4205.94,884.23) 1(4209.6,641.33) 1(4209.6,641.33) 1(4209.64,1178.48) 1(4209.64,1178.48) 1(4213.08,698.1) 1(4213.08,698.1) 1(4213.64,999.83) 1(4213.64,999.83) 1(4217.57,170.59) 1(4217.57,170.59) 1(4217.57,1235.19) 1(4217.57,1235.19) 1(4219.9,452.91) 1(4219.9,452.91) 1(4220.12,982.97) 1(4220.12,982.97) 1(4224.03,1191.72) 1(4224.03,1191.72) 1(4226.03,1123.68) 1(4226.03,1123.68) 1(4226.67,865.67) 1(4226.67,865.67) 1(4230.92,1079.13) 1(4230.92,1079.13) 1(4231.18,926.81) 1(4231.18,926.81) 1(4231.65,1394.98) 1(4231.65,1394.98) 1(4236.18,1253.35) 1(4236.18,1253.35) 1(4244.5,335.98) 1(4244.5,335.98) 1(4245.78,1219.29) 1(4245.78,1219.29) 1(4247.81,772.59) 1(4247.81,772.59) 1(4254.68,899.66) 1(4254.68,899.66) 1(4260.82,977.72) 1(4260.82,977.72) 1(4260.82,1028.9) 1(4260.82,1028.9) 1(4260.82,1131.27) 1(4260.82,1131.27) 1(4260.82,1080.09) 1(4260.82,1080.09) 1(4261.48,1424.05) 1(4261.48,1424.05) 1(4264.48,939.17) 1(4264.48,939.17) 1(4266.66,1198.5) 1(4266.66,1198.5) 1(4266.83,273.61) 1(4266.83,273.61) 1(4266.94,607.69) 1(4266.94,607.69) 1(4268.07,1252.23) 1(4268.07,1252.23) 1(4269.04,872.85) 1(4269.04,872.85) 1(4273.62,1164.95) 1(4273.62,1164.95) 1(4278.54,466.94) 1(4278.54,466.94) 1(4285.57,348.35) 1(4285.57,348.35) 1(4286.41,1003.31) 1(4286.41,1003.31) 1(4286.41,1054.49) 1(4286.41,1054.49) 1(4286.41,1105.68) 1(4286.41,1105.68) 1(4287.24,1236.62) 1(4287.24,1236.62) 1(4300.98,1555.44) 1(4300.98,1555.44) 1(4302.23,1212.56) 1(4302.23,1212.56) 1(4304.58,1703.43) 1(4304.58,1703.43) 1(4305.32,1627.88) 1(4305.32,1627.88) 1(4307.44,604.57) 1(4307.44,604.57) 1(4310.96,950.85) 1(4310.96,950.85) 1(4311.13,458.69) 1(4311.13,458.69) 1(4312.01,977.72) 1(4312.01,977.72) 1(4312.01,1028.9) 1(4312.01,1028.9) 1(4312.01,1080.09) 1(4312.01,1080.09) 1(4312.01,1131.27) 1(4312.01,1131.27) 1(4314.84,862.84) 1(4314.84,862.84) 1(4314.89,1168.56) 1(4314.89,1168.56) 1(4318.94,916.13) 1(4318.94,916.13) 1(4322.65,380.25) 1(4322.65,380.25) 1(4326.84,1231.96) 1(4326.84,1231.96) 1(4328.28,1678.05) 1(4328.28,1678.05) 1(4334.68,1202.43) 1(4334.68,1202.43) 1(4336.23,613.95) 1(4336.23,613.95) 1(4337.6,1003.31) 1(4337.6,1003.31) 1(4337.6,1054.49) 1(4337.6,1054.49) 1(4337.6,1105.68) 1(4337.6,1105.68) 1(4338.31,1251.74) 1(4338.31,1251.74) 1(4338.53,870.34) 1(4338.53,870.34) 1(4341.16,1399.74) 1(4341.16,1399.74) 1(4351.18,856.94) 1(4351.18,856.94) 1(4356.44,1188.2) 1(4356.44,1188.2) 1(4357.72,468.74) 1(4357.72,468.74) 1(4359.67,579.37) 1(4359.67,579.37) 1(4362.66,1160.97) 1(4362.66,1160.97) 1(4363.19,954.32) 1(4363.19,954.32) 1(4363.19,977.72) 1(4363.19,977.72) 1(4363.19,1028.9) 1(4363.19,1028.9) 1(4363.19,1080.09) 1(4363.19,1080.09) 1(4363.19,1131.27) 1(4363.19,1131.27) 1(4364.52,1254.55) 1(4364.52,1254.55) 1(4373.26,1617.15) 1(4373.26,1617.15) 1(4373.97,1225.78) 1(4373.97,1225.78) 1(4379.19,1469.07) 1(4379.19,1469.07) 1(4381.29,1650.98) 1(4381.29,1650.98) 1(4387.64,888.58) 1(4387.64,888.58) 1(4388.78,1003.31) 1(4388.78,1003.31) 1(4388.78,1054.49) 1(4388.78,1054.49) 1(4388.78,1105.68) 1(4388.78,1105.68) 1(4390.25,862.25) 1(4390.25,862.25) 1(4392.59,338.88) 1(4392.59,338.88) 1(4392.89,918.18) 1(4392.89,918.18) 1(4394.89,1992.36) 1(4394.89,1992.36) 1(4396.48,398.88) 1(4396.48,398.88) 1(4399.51,574.83) 1(4399.51,574.83) 1(4403.62,1423.67) 1(4403.62,1423.67) 1(4404.47,470.91) 1(4404.47,470.91) 1(4407.15,1234.31) 1(4407.15,1234.31) 1(4407.45,1195.74) 1(4407.45,1195.74) 1(4413.59,1165.65) 1(4413.59,1165.65) 1(4414.37,977.72) 1(4414.37,977.72) 1(4414.37,1028.9) 1(4414.37,1028.9) 1(4414.37,1080.09) 1(4414.37,1080.09) 1(4414.37,1131.27) 1(4414.37,1131.27) 1(4415.65,951.09) 1(4415.65,951.09) 1(4416.04,862.84) 1(4416.04,862.84) 1(4430.08,895.21) 1(4430.08,895.21) 1(4431.86,354.78) 1(4431.86,354.78) 1(4438.87,1213.91) 1(4438.87,1213.91) 1(4443.63,274.06) 1(4443.63,274.06) 1(4448.4,1126.08) 1(4448.4,1126.08) 1(4448.71,980.87) 1(4448.71,980.87) 1(4449.31,462.92) 1(4449.31,462.92) 1(4452.58,1076.43) 1(4452.58,1076.43) 1(4454.04,1189.46) 1(4454.04,1189.46) 1(4455.07,1244.11) 1(4455.07,1244.11) 1(4455.49,1670.69) 1(4455.49,1670.69) 1(4455.5,923.12) 1(4455.5,923.12) 1(4455.96,1032.77) 1(4455.96,1032.77) 1(4456.52,860.06) 1(4456.52,860.06) 1(4459.53,1639.69) 1(4459.53,1639.69) 1(4466.18,355.38) 1(4466.18,355.38) 1(4470.3,888.73) 1(4470.3,888.73) 1(4471.45,995.6) 1(4471.45,995.6) 1(4473.15,1483.49) 1(4473.15,1483.49) 1(4474.05,1121.85) 1(4474.05,1121.85) 1(4474.33,586.05) 1(4474.33,586.05) 1(4478.28,1063.05) 1(4478.28,1063.05) 1(4479.82,1159.59) 1(4479.82,1159.59) 1(4479.84,949.15) 1(4479.84,949.15) 1(4481.87,1221.18) 1(4481.87,1221.18) 1(4481.93,1031.41) 1(4481.93,1031.41) 1(4491.93,1253.31) 1(4491.93,1253.31) 1(4494.25,469.54) 1(4494.25,469.54) 1(4496.21,1090.65) 1(4496.21,1090.65) 1(4500.08,909.51) 1(4500.08,909.51) 1(4502.64,1717.34) 1(4502.64,1717.34) 1(4503.77,579.16) 1(4503.77,579.16) 1(4505.56,1192.22) 1(4505.56,1192.22) 1(4505.78,1134.2) 1(4505.78,1134.2) 1(4507.01,344.15) 1(4507.01,344.15) 1(4508.02,1677.13) 1(4508.02,1677.13) 1(4509.06,1235.1) 1(4509.06,1235.1) 1(4513.35,1017.16) 1(4513.35,1017.16) 1(4514.3,965.82) 1(4514.3,965.82) 1(4519.1,1581.14) 1(4519.1,1581.14) 1(4523.28,1105.32) 1(4523.28,1105.32) 1(4523.49,936.34) 1(4523.49,936.34) 1(4526.19,898.04) 1(4526.19,898.04) 1(4526.8,1507.11) 1(4526.8,1507.11) 1(4528.15,759.68) 1(4528.15,759.68) 1(4529.28,1070.51) 1(4529.28,1070.51) 1(4531.32,1173.32) 1(4531.32,1173.32) 1(4531.57,991.02) 1(4531.57,991.02) 1(4531.79,1039.99) 1(4531.79,1039.99) 1(4532.97,1477.33) 1(4532.97,1477.33) 1(4533.99,1129.08) 1(4533.99,1129.08) 1(4535.54,1210.46) 1(4535.54,1210.46) 1(4536.77,1236.43) 1(4536.77,1236.43) 1(4538.33,287.89) 1(4538.33,287.89) 1(4542.05,462.78) 1(4542.05,462.78) 1(4548.76,355.38) 1(4548.76,355.38) 1(4552.14,595.64) 1(4552.14,595.64) 1(4556.67,1519.78) 1(4556.67,1519.78) 1(4557.1,-65.85) 1(4557.1,-65.85) 1(4584.64,-56.5) 1(4584.64,-56.5) 1(4587.15,1595.01) 1(4587.15,1595.01) 1(4587.26,286.14) 1(4587.26,286.14) 1(4593.33,346.2) 1(4593.33,346.2) 1(4595.63,594.82) 1(4595.63,594.82) 1(4606.77,1456.95) 1(4606.77,1456.95) 1(4609.23,1312.59) 1(4609.23,1312.59) 1(4609.47,1497.17) 1(4609.47,1497.17) 1(4610.24,-66.03) 1(4610.24,-66.03) 1(4611,2109) 1(4611,2109) 1(4615.01,805.06) 1(4615.01,805.06) 1(4615.43,1717.33) 1(4615.43,1717.33) 1(4622.48,455.54) 1(4622.48,455.54) 1(4634.12,322) 1(4634.12,322) 1(4637.38,601.94) 1(4637.38,601.94) 1(4637.71,571.65) 1(4637.71,571.65) 1(4647.07,1471.68) 1(4647.07,1471.68) 1(4654.17,1642.35) 1(4654.17,1642.35) 1(4657.76,459.03) 1(4657.76,459.03) 1(4659.77,350.75) 1(4659.77,350.75) 1(4662.59,1409.48) 1(4662.59,1409.48) 1(4671.66,576.85) 1(4671.66,576.85) 1(4690.09,1577.76) 1(4690.09,1577.76) 1(4692.03,1691.44) 1(4692.03,1691.44) 1(4693.83,344.15) 1(4693.83,344.15) 1(4702.6,457.77) 1(4702.6,457.77) 1(4706.85,1495.3) 1(4706.85,1495.3) 1(4711,2109) 1(4711,2109) 1(4726.28,1025.38) 1(4726.28,1025.38) 1(4726.83,1525.28) 1(4726.83,1525.28) 1(4738.43,942.93) 1(4738.43,942.93) 1(4743.34,460.26) 1(4743.34,460.26) 1(4744.79,799.61) 1(4744.79,799.61) 1(4748.31,348.99) 1(4748.31,348.99) 1(4749.38,602.91) 1(4749.38,602.91) 1(4773.49,1475.03) 1(4773.49,1475.03) 1(4774.52,1693.9) 1(4774.52,1693.9) 1(4781.56,343.91) 1(4781.56,343.91) 1(4782.87,1157.62) 1(4782.87,1157.62) 1(4783.61,1241.52) 1(4783.61,1241.52) 1(4789.92,461.94) 1(4789.92,461.94) 1(4794.56,855.91) 1(4794.56,855.91) 1(4795.12,940.61) 1(4795.12,940.61) 1(4795.88,1772.13) 1(4795.88,1772.13) 1(4800.44,1568.29) 1(4800.44,1568.29) 1(4811,2109) 1(4811,2109) 1(4825.12,1725.4) 1(4825.12,1725.4) 1(4825.38,1591.58) 1(4825.38,1591.58) 1(4833,1082) 1(4833,1082) 1(4834.61,1305.87) 1(4834.61,1305.87) 1(4834.81,1210.83) 1(4834.81,1210.83) 1(4835.37,1272.01) 1(4835.37,1272.01) 1(4838.74,814.75) 1(4838.74,814.75) 1(4840.16,1170.42) 1(4840.16,1170.42) 1(4841.25,310.38) 1(4841.25,310.38) 1(4841.82,656.33) 1(4841.82,656.33) 1(4841.82,1022.11) 1(4841.82,1022.11) 1(4865.97,1466.59) 1(4865.97,1466.59) 1(4867,1358) 1(4867,1358) 1(4872,464) 1(4872,464) 1(4875.21,1425.28) 1(4875.21,1425.28) 1(4876.25,996.14) 1(4876.25,996.14) 1(4877.35,432.84) 1(4877.35,432.84) 1(4878.89,1084.27) 1(4878.89,1084.27) 1(4879.08,1149.76) 1(4879.08,1149.76) 1(4881.08,1204.76) 1(4881.08,1204.76) 1(4881.77,1304.75) 1(4881.77,1304.75) 1(4883.27,1270.62) 1(4883.27,1270.62) 1(4884.98,1037.73) 1(4884.98,1037.73) 1(4891.02,1685.18) 1(4891.02,1685.18) 1(4895.19,616.35) 1(4895.19,616.35) 1(4916.62,2098.46) 1(4916.62,2098.46) 1(4916.64,1712.57) 1(4916.64,1712.57) 1(4925.1,1487.93) 1(4925.1,1487.93) 1(4927.13,366.88) 1(4927.13,366.88) 1(4931.51,1162.23) 1(4931.51,1162.23) 1(4933.45,1427.73) 1(4933.45,1427.73) 1(4934.45,1042.98) 1(4934.45,1042.98) 1(4934.62,1565.65) 1(4934.62,1565.65) 1(4941.07,95.54) 1(4941.07,95.54) 1(4971.28,440.27) 1(4971.28,440.27) 1(4972.77,613.42) 1(4972.77,613.42) 1(4982.38,1237.96) 1(4982.38,1237.96) 1(4984.52,1077.56) 1(4984.52,1077.56) 1(4984.52,1120.73) 1(4984.52,1120.73) 1(4986.77,1416.83) 1(4986.77,1416.83) 1(4986.85,977.38) 1(4986.85,977.38) 1(4987.57,1374.48) 1(4987.57,1374.48) 1(4988.9,1490.44) 1(4988.9,1490.44) 1(4994.46,1996.71) 1(4994.46,1996.71) 1(4995.64,503.19) 1(4995.64,503.19) 1(4996,26) 1(4996,26) 1(5005.98,1538.06) 1(5005.98,1538.06) 1(5006,1577.64) 1(5006,1577.64) 1(5011,2109) 1(5011,2109) 1(5017.69,1791.39) 1(5017.69,1791.39) 1(5028.41,1647.88) 1(5028.41,1647.88) 1(5030.29,429.03) 1(5030.29,429.03) 1(5030.62,516.78) 1(5030.62,516.78) 1(5041.94,977.15) 1(5041.94,977.15) 1(5043.6,1351.96) 1(5043.6,1351.96) 1(5053.84,1707.81) 1(5053.84,1707.81) 1(5061.73,1040.49) 1(5061.73,1040.49) 1(5067.57,2014.55) 1(5067.57,2014.55) 1(5070.7,1415.74) 1(5070.7,1415.74) 1(5071,1813) 1(5071,1813) 1(5083.64,977.48) 1(5083.64,977.48) 1(5085.72,922.47) 1(5085.72,922.47) 1(5086.24,816.26) 1(5086.24,816.26) 1(5087.15,878.28) 1(5087.15,878.28) 1(5092.59,1874.13) 1(5092.59,1874.13) 1(5103.22,1652.61) 1(5103.22,1652.61) 1(5105.92,1801.13) 1(5105.92,1801.13) 1(5111,2109) 1(5111,2109) 1(5111.94,429.89) 1(5111.94,429.89) 1(5115.64,1015.56) 1(5115.64,1015.56) 1(5119.23,1340.92) 1(5119.23,1340.92) 1(5119.23,1539.57) 1(5119.23,1539.57) 1(5126.1,1173.28) 1(5126.1,1173.28) 1(5133.2,1297.43) 1(5133.2,1297.43) 1(5137.84,1810.29) 1(5137.84,1810.29) 1(5140.11,1626.37) 1(5140.11,1626.37) 1(5141.97,1861.36) 1(5141.97,1861.36) 1(5149.2,1141.68) 1(5149.2,1141.68) 1(5159.85,633.29) 1(5159.85,633.29) 1(5166.43,932.5) 1(5166.43,932.5) 1(5166.89,977.69) 1(5166.89,977.69) 1(5168.32,854.31) 1(5168.32,854.31) 1(5173.11,737.44) 1(5173.11,737.44) 1(5173.11,777.03) 1(5173.11,777.03) 1(5175.93,1830.51) 1(5175.93,1830.51) 1(5177.38,1269.55) 1(5177.38,1269.55) 1(5183.28,2014.94) 1(5183.28,2014.94) 1(5184.36,1131.22) 1(5184.36,1131.22) 1(5194.32,369.02) 1(5194.32,369.02) 1(5203.87,1039.77) 1(5203.87,1039.77) 1(5208.53,1200.08) 1(5208.53,1200.08) 1(5211,2109) 1(5211,2109) 1(5225.88,776.98) 1(5225.88,776.98) 1(5225.88,737.61) 1(5225.88,737.61) 1(5226.57,979.11) 1(5226.57,979.11) 1(5227.22,934.46) 1(5227.22,934.46) 1(5227.45,820.93) 1(5227.45,820.93) 1(5228.77,855.72) 1(5228.77,855.72) 1(5231.95,698.23) 1(5231.95,698.23) 1(5254,576) 1(5254,576) 1(5258.87,1147.65) 1(5258.87,1147.65) 1(5263.64,1200.11) 1(5263.64,1200.11) 1(5276,-115) 1(5276,-115) 1(5309.26,1203.92) 1(5309.26,1203.92) 1(5311,376) 1(5311,376) 1(5311,2109) 1(5311,2109) 1(5316.52,1799.55) 1(5316.52,1799.55) 1(5321.53,1429.88) 1(5321.53,1429.88) 1(5321.75,1141.1) 1(5321.75,1141.1) 1(5331.52,1548.78) 1(5331.52,1548.78) 1(5343.46,1175.91) 1(5343.46,1175.91) 1(5350.99,257.78) 1(5350.99,257.78) 1(5374,375) 1(5374,375) 1(5376,-115) 1(5376,-115) 1(5376.52,1789.73) 1(5376.52,1789.73) 1(5382.64,1408.84) 1(5382.64,1408.84) 1(5411,2109) 1(5411,2109) 1(5416,1539) 1(5416,1539) 1(5416.82,1569.33) 1(5416.82,1569.33) 1(5416.82,1370.73) 1(5416.82,1370.73) 1(5417.64,1059.69) 1(5417.64,1059.69) 1(5424.23,1015.58) 1(5424.23,1015.58) 1(5439,836) 1(5439,836) 1(5445.58,689.03) 1(5445.58,689.03) 1(5448.47,228.03) 1(5448.47,228.03) 1(5451.52,1540.83) 1(5451.52,1540.83) 1(5451.52,1789.73) 1(5451.52,1789.73) 1(5453.42,1138.88) 1(5453.42,1138.88) 1(5454.54,1341.76) 1(5454.54,1341.76) 1(5455,1376) 1(5455,1376) 1(5455,1410) 1(5455,1410) 1(5458,1102) 1(5458,1102) 1(5460,372) 1(5460,372) 1(5460.35,568.53) 1(5460.35,568.53) 1(5469.57,623.65) 1(5469.57,623.65) 1(5474.54,982.98) 1(5474.54,982.98) 1(5476,-115) 1(5476,-115) 1(5476.16,934.46) 1(5476.16,934.46) 1(5477.58,737.18) 1(5477.58,737.18) 1(5481.73,166.42) 1(5481.73,166.42) 1(5488.74,1133) 1(5488.74,1133) 1(5494.06,894.07) 1(5494.06,894.07) 1(5496.36,1378.35) 1(5496.36,1378.35) 1(5506.27,1541.55) 1(5506.27,1541.55) 1(5511,2109) 1(5511,2109) 1(5511.52,1799.55) 1(5511.52,1799.55) 1(5547.45,697.5) 1(5547.45,697.5) 1(5547.45,1397.82) 1(5547.45,1397.82) 1(5548.23,1244.66) 1(5548.23,1244.66) 1(5560.85,598.43) 1(5560.85,598.43) 1(5561.09,810.56) 1(5561.09,810.56) 1(5568.23,902.32) 1(5568.23,902.32) 1(5568.23,1003.98) 1(5568.23,1003.98) 1(5572.32,1211.87) 1(5572.32,1211.87) 1(5575.69,1539.4) 1(5575.69,1539.4) 1(5575.69,1789.73) 1(5575.69,1789.73) 1(5576,-115) 1(5576,-115) 1(5576.67,777.97) 1(5576.67,777.97) 1(5580.01,1154.36) 1(5580.01,1154.36) 1(5581.02,1412.76) 1(5581.02,1412.76) 1(5588.38,1048.21) 1(5588.38,1048.21) 1(5588.66,860.76) 1(5588.66,860.76) 1(5611,2109) 1(5611,2109) 1(5618.64,1415.36) 1(5618.64,1415.36) 1(5627.15,1151.35) 1(5627.15,1151.35) 1(5635.37,1553.4) 1(5635.37,1553.4) 1(5635.69,1799.55) 1(5635.69,1799.55) 1(5647.75,766.53) 1(5647.75,766.53) 1(5647.75,972.46) 1(5647.75,972.46) 1(5651.46,864.43) 1(5651.46,864.43) 1(5651.69,663.42) 1(5651.69,663.42) 1(5654.03,1117.71) 1(5654.03,1117.71) 1(5672.45,737.41) 1(5672.45,737.41) 1(5676,-115) 1(5676,-115) 1(5686.11,864.75) 1(5686.11,864.75) 1(5689.09,972.46) 1(5689.09,972.46) 1(5695.69,1785.71) 1(5695.69,1785.71) 1(5711,2109) 1(5711,2109) 1(5714.39,647.95) 1(5714.39,647.95) 1(5728.81,1159.93) 1(5728.81,1159.93) 1(5728.81,1566.41) 1(5728.81,1566.41) 1(5737.89,1207.4) 1(5737.89,1207.4) 1(5740,387) 1(5740,387) 1(5740.27,1330.03) 1(5740.27,1330.03) 1(5746.91,827.76) 1(5746.91,827.76) 1(5749.1,732.7) 1(5749.1,732.7) 1(5749.1,775.07) 1(5749.1,775.07) 1(5755.22,505.29) 1(5755.22,505.29) 1(5760.91,875.64) 1(5760.91,875.64) 1(5760.91,917.95) 1(5760.91,917.95) 1(5760.91,967) 1(5760.91,967) 1(5761.93,1015.72) 1(5761.93,1015.72) 1(5767.94,303.16) 1(5767.94,303.16) 1(5771.53,1841.58) 1(5771.53,1841.58) 1(5776,-115) 1(5776,-115) 1(5784,1211) 1(5784,1211) 1(5788.37,112.3) 1(5788.37,112.3) 1(5798.69,152.33) 1(5798.69,152.33) 1(5799.88,382.57) 1(5799.88,382.57) 1(5800.66,1777.31) 1(5800.66,1777.31) 1(5801.75,1433.61) 1(5801.75,1433.61) 1(5811,2109) 1(5811,2109) 1(5812.07,89.95) 1(5812.07,89.95) 1(5827.65,1801.13) 1(5827.65,1801.13) 1(5830.57,1423.66) 1(5830.57,1423.66) 1(5832.8,704.92) 1(5832.8,704.92) 1(5833.9,1211.87) 1(5833.9,1211.87) 1(5836.93,806.29) 1(5836.93,806.29) 1(5838.48,1042.63) 1(5838.48,1042.63) 1(5853.27,1451.73) 1(5853.27,1451.73) 1(5860.13,447.11) 1(5860.13,447.11) 1(5861,678) 1(5861,678) 1(5861.43,229.66) 1(5861.43,229.66) 1(5861.48,1331.19) 1(5861.48,1331.19) 1(5869.3,1417.16) 1(5869.3,1417.16) 1(5873,835) 1(5873,835) 1(5876,-115) 1(5876,-115) 1(5884,1022) 1(5884,1022) 1(5894.5,1609.69) 1(5894.5,1609.69) 1(5894.5,1674.05) 1(5894.5,1674.05) 1(5894.5,1736.2) 1(5894.5,1736.2) 1(5904.59,1450.59) 1(5904.59,1450.59) 1(5905,1052) 1(5905,1052) 1(5905.3,1418.94) 1(5905.3,1418.94) 1(5911,2109) 1(5911,2109) 1(5914,731) 1(5914,731) 1(5922.58,668.82) 1(5922.58,668.82) 1(5929,1023) 1(5929,1023) 1(5929.42,922.71) 1(5929.42,922.71) 1(5929.42,968.97) 1(5929.42,968.97) 1(5933.83,1768.87) 1(5933.83,1768.87) 1(5933.83,1703.75) 1(5933.83,1703.75) 1(5937.57,1408.09) 1(5937.57,1408.09) 1(5948.78,1639.76) 1(5948.78,1639.76) 1(5949.57,195.12) 1(5949.57,195.12) 1(5954.4,322.78) 1(5954.4,322.78) 1(5957.45,1248.29) 1(5957.45,1248.29) 1(5960.46,418.23) 1(5960.46,418.23) 1(5965.47,-17.99) 1(5965.47,-17.99) 1(5971.5,1929.49) 1(5971.5,1929.49) 1(5976,-115) 1(5976,-115) 1(5976.47,1087.55) 1(5976.47,1087.55) 1(6000.23,775.07) 1(6000.23,775.07) 1(6003.63,1373.63) 1(6003.63,1373.63) 1(6004.36,667.24) 1(6004.36,667.24) 1(6006.75,1428.12) 1(6006.75,1428.12) 1(6006.75,1901.33) 1(6006.75,1901.33) 1(6011,2109) 1(6011,2109) 1(6017.55,396.47) 1(6017.55,396.47) 1(6019.81,1624.58) 1(6019.81,1624.58) 1(6023.05,1736.89) 1(6023.05,1736.89) 1(6024,985) 1(6024,985) 1(6025.31,219.06) 1(6025.31,219.06) 1(6025.32,1674.05) 1(6025.32,1674.05) 1(6027.5,500.16) 1(6027.5,500.16) 1(6028.19,1577.21) 1(6028.19,1577.21) 1(6029.56,1294.76) 1(6029.56,1294.76) 1(6034.98,1082.39) 1(6034.98,1082.39) 1(6043.54,1426.39) 1(6043.54,1426.39) 1(6046.78,781.31) 1(6046.78,781.31) 1(6059,2058)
